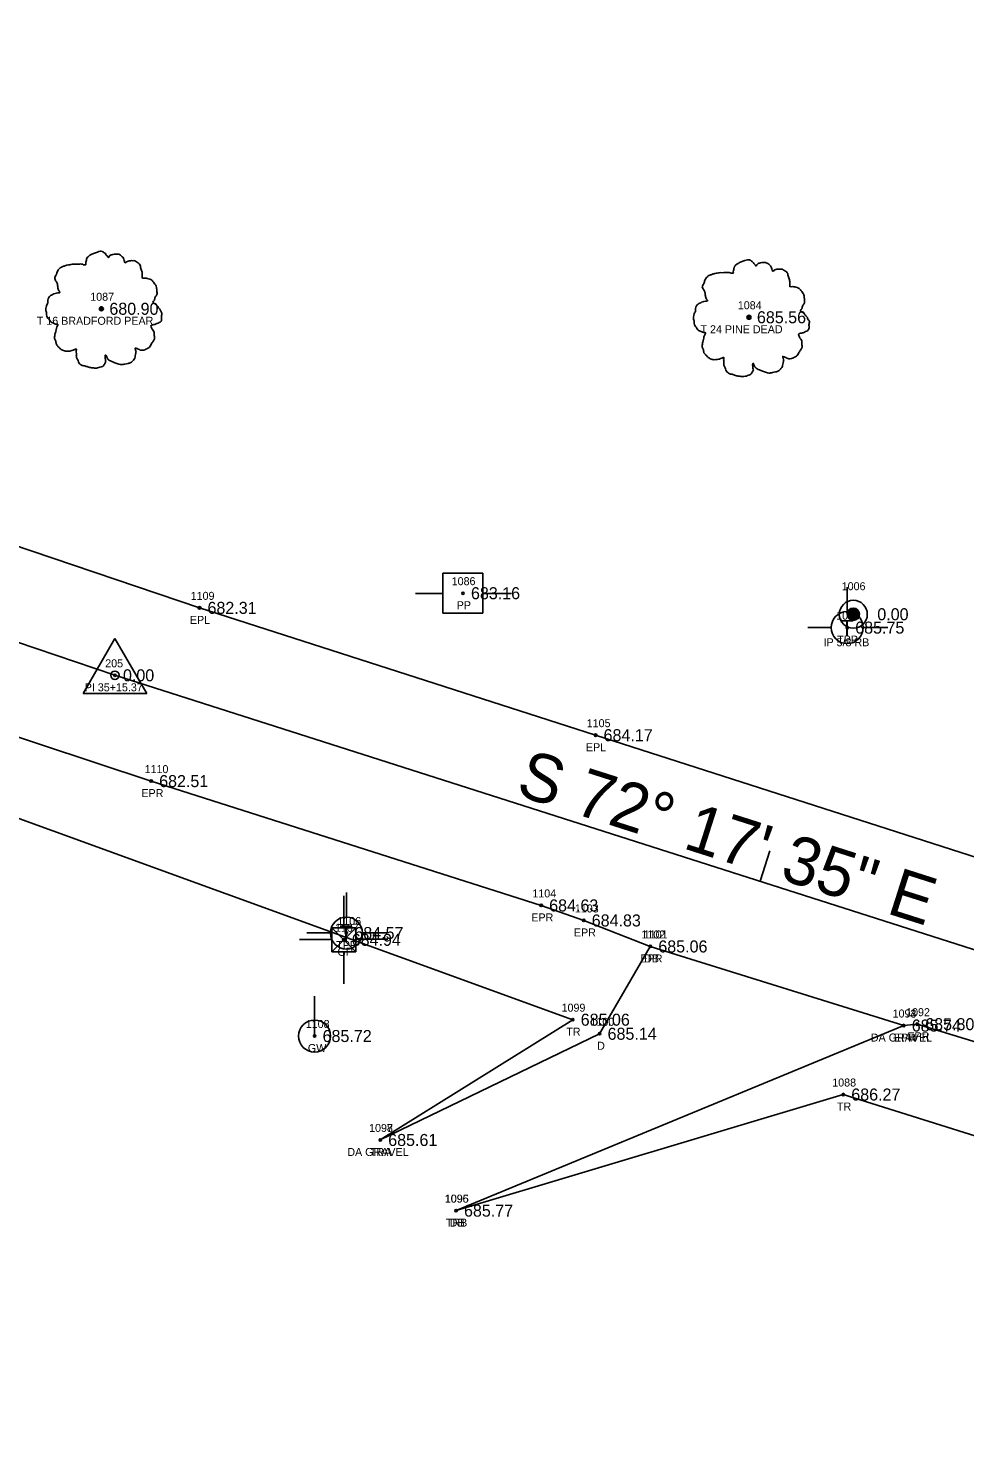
# Model space of a CAD drawing. Extents: x 1655137 to 1657928, y 1003994 to 1005407.
# Drawn here: x 1656847.1 to 1656964.1, y 1004369.3 to 1004544.3 of the extents above; entities that cross this region are included whole.
import ezdxf

# ---------------------------------------------------------------- set-up
doc = ezdxf.new("R2010")
doc.units = 0
for name, color, linetype in [('RD_EX_Driveway', 7, 'Continuous'), ('RD_EX_Driveway_txCode', 7, 'Continuous'), ('RD_EX_DV_Prop_txCode', 7, 'Continuous'), ('RD_EX_DV_PropPin', 7, 'Continuous'), ('RD_EX_Road', 7, 'Continuous'), ('RD_EX_Road_txCode', 7, 'Continuous'), ('RD_EX_TX_Driveway_ELEV', 7, 'Continuous'), ('RD_EX_TX_DV_Prop_ELEV', 7, 'Continuous'), ('RD_EX_TX_Road_ELEV', 7, 'Continuous'), ('RD_EX_TX_UT_ELEV', 7, 'Continuous'), ('RD_EX_TX_VEG_ELEV', 7, 'Continuous'), ('RD_EX_UT', 7, 'Continuous'), ('RD_EX_UT_txCode', 7, 'Continuous'), ('RD_EX_VEG', 7, 'Continuous'), ('RD_EX_VEG_txCode', 7, 'Continuous'), ('RD_HC_Cl', 7, 'Continuous'), ('RD_HC_Data', 7, 'Continuous'), ('RD_HC_Data_Tic', 7, 'Continuous'), ('RD_HC_Survey_ELEV', 7, 'Continuous'), ('RD_HC_txCode', 7, 'Continuous'), ('RD_SMD_Locator', 7, 'Continuous')]:
    doc.layers.add(name, color=color, linetype=linetype)

msp = doc.modelspace()

# ---------------------------------------------------------------- linework, layer by layer
at = {"layer": 'RD_EX_Driveway'}
msp.add_line((1656956.49, 1004419.67), (1656900.55, 1004396.54), dxfattribs=at)
msp.add_lwpolyline([(1656891.08, 1004405.37), (1656918.49, 1004418.64), (1656924.83, 1004429.55)], dxfattribs=at)
at = {"layer": 'RD_EX_DV_PropPin'}
for p, q in [((1656949.46, 1004470.87), (1656949.46, 1004471.26)), ((1656949.49, 1004470.76), (1656949.49, 1004471.36)), ((1656949.53, 1004470.69), (1656949.53, 1004471.43)), ((1656949.56, 1004470.64), (1656949.56, 1004471.49)), ((1656949.6, 1004470.59), (1656949.6, 1004471.54)), ((1656949.63, 1004470.55), (1656949.63, 1004471.58)), ((1656949.67, 1004470.51), (1656949.67, 1004471.61)), ((1656949.7, 1004470.48), (1656949.7, 1004471.64)), ((1656949.74, 1004470.45), (1656949.74, 1004471.67)), ((1656949.77, 1004470.43), (1656949.77, 1004471.7)), ((1656949.81, 1004470.41), (1656949.81, 1004471.72)), ((1656949.84, 1004470.39), (1656949.84, 1004471.74)), ((1656949.88, 1004470.37), (1656949.88, 1004471.75)), ((1656949.91, 1004470.35), (1656949.91, 1004471.77)), ((1656949.95, 1004470.34), (1656949.95, 1004471.78)), ((1656949.98, 1004470.33), (1656949.98, 1004471.79)), ((1656950.02, 1004470.32), (1656950.02, 1004471.8)), ((1656950.05, 1004470.31), (1656950.05, 1004471.81)), ((1656950.09, 1004470.31), (1656950.09, 1004471.82)), ((1656950.12, 1004470.3), (1656950.12, 1004471.82)), ((1656950.16, 1004470.3), (1656950.16, 1004471.82)), ((1656950.19, 1004470.3), (1656950.19, 1004471.82)), ((1656950.23, 1004470.3), (1656950.23, 1004471.82)), ((1656950.26, 1004470.3), (1656950.26, 1004471.82)), ((1656950.3, 1004470.31), (1656950.3, 1004471.82)), ((1656950.33, 1004470.31), (1656950.33, 1004471.81)), ((1656950.37, 1004470.32), (1656950.37, 1004471.8)), ((1656950.4, 1004470.33), (1656950.4, 1004471.79)), ((1656950.44, 1004470.34), (1656950.44, 1004471.78)), ((1656950.47, 1004470.35), (1656950.47, 1004471.77)), ((1656950.51, 1004470.37), (1656950.51, 1004471.75)), ((1656950.54, 1004470.39), (1656950.54, 1004471.74)), ((1656950.58, 1004470.41), (1656950.58, 1004471.72)), ((1656950.61, 1004470.43), (1656950.61, 1004471.7)), ((1656950.65, 1004470.45), (1656950.65, 1004471.67)), ((1656950.68, 1004470.48), (1656950.68, 1004471.64)), ((1656950.72, 1004470.51), (1656950.72, 1004471.61)), ((1656950.75, 1004470.55), (1656950.75, 1004471.58)), ((1656950.79, 1004470.59), (1656950.79, 1004471.54)), ((1656950.82, 1004470.64), (1656950.82, 1004471.49)), ((1656950.86, 1004470.69), (1656950.86, 1004471.43)), ((1656950.89, 1004470.76), (1656950.89, 1004471.36)), ((1656950.93, 1004470.87), (1656950.93, 1004471.26))]:
    msp.add_line(p, q, dxfattribs=at)
for radius in [1.75, 0.761]:
    msp.add_circle((1656950.19, 1004471.06), radius, dxfattribs=at)
at = {"layer": 'RD_EX_Road'}
for points in [[(1657064.39, 1004409.09), (1657015.67, 1004424.64), (1656965.82, 1004440.6), (1656917.99, 1004455.95), (1656868.5, 1004471.86), (1656826.53, 1004486.06), (1656801.74, 1004494.51), (1656772.14, 1004504.27), (1656723.45, 1004520.92), (1656674.94, 1004537.34), (1656626.5, 1004553.88), (1656578.27, 1004569.52), (1656529.18, 1004584.75), (1656481.5, 1004600.51), (1656432.67, 1004617.14), (1656404.34, 1004625.82)], [(1657057.77, 1004388.92), (1657009.7, 1004404.08), (1656958.18, 1004419.84), (1656956.49, 1004419.67), (1656924.83, 1004429.55), (1656916.51, 1004432.8), (1656911.19, 1004434.68), (1656862.46, 1004450.21), (1656813.53, 1004466.42), (1656765.51, 1004482.33), (1656716.81, 1004499.14), (1656668.6, 1004515.93), (1656620.24, 1004532.54), (1656571.72, 1004548.37), (1656523.3, 1004563.77), (1656474.37, 1004580.29), (1656426.43, 1004596.82), (1656398.22, 1004606.78)]]:
    msp.add_lwpolyline(points, dxfattribs=at)
at = {"layer": 'RD_EX_UT'}
for p, q in [((1656903.91, 1004476.2), (1656898.91, 1004476.2)), ((1656898.91, 1004476.2), (1656898.91, 1004471.2)), ((1656903.91, 1004471.2), (1656903.91, 1004476.2)), ((1656949.43, 1004474.46), (1656949.43, 1004471.39)), ((1656895.48, 1004473.64), (1656898.95, 1004473.64)), ((1656903.84, 1004473.64), (1656907.48, 1004473.64)), ((1656898.91, 1004471.2), (1656903.91, 1004471.2)), ((1656944.5, 1004469.41), (1656947.43, 1004469.41)), ((1656951.43, 1004469.41), (1656954.5, 1004469.41)), ((1656886.52, 1004431.88), (1656886.52, 1004435.88)), ((1656886.85, 1004436.3), (1656886.85, 1004433.23)), ((1656885, 1004430.43), (1656881, 1004430.43)), ((1656881.92, 1004431.25), (1656884.85, 1004431.25)), ((1656888.02, 1004431.88), (1656885.02, 1004428.88)), ((1656885.02, 1004431.88), (1656888.02, 1004428.88)), ((1656888.02, 1004431.88), (1656885.02, 1004431.88)), ((1656885.02, 1004431.88), (1656885.02, 1004428.88)), ((1656888.02, 1004428.88), (1656888.02, 1004431.88)), ((1656888.04, 1004430.45), (1656892.05, 1004430.45)), ((1656888.85, 1004431.25), (1656891.92, 1004431.25)), ((1656885.02, 1004428.88), (1656888.02, 1004428.88)), ((1656886.52, 1004428.88), (1656886.52, 1004424.88)), ((1656882.88, 1004418.36), (1656882.88, 1004423.36))]:
    msp.add_line(p, q, dxfattribs=at)
for centre in [(1656949.43, 1004469.39), (1656886.85, 1004431.23), (1656882.88, 1004418.36)]:
    msp.add_circle(centre, 2, dxfattribs=at)
at = {"layer": 'RD_EX_VEG'}
for points in [[(1656891.08, 1004405.37), (1656915.13, 1004420.4), (1656763.49, 1004475.48), (1656570, 1004542.2), (1656467.82, 1004565.09), (1656367.55, 1004594.62), (1656280.9, 1004634.63), (1656273.57, 1004608.65)], [(1657052.06, 1004369.26), (1656992.01, 1004397.53), (1656948.94, 1004411.05), (1656900.55, 1004396.54)]]:
    msp.add_lwpolyline(points, dxfattribs=at)
for centre, radius in [((1656856.24, 1004509.23), 0.25), ((1656856.22, 1004509.21), 0.0001), ((1656937.15, 1004508.17), 0.25), ((1656937.13, 1004508.15), 0.0001)]:
    msp.add_circle(centre, radius, dxfattribs=at)
for points in [[(1656856.37, 1004516.39), (1656856.07, 1004516.42), (1656855.74, 1004516.32), (1656855.49, 1004516.22), (1656855.27, 1004516.14), (1656855.04, 1004516.04), (1656854.74, 1004515.87), (1656854.52, 1004515.67), (1656854.39, 1004515.42), (1656854.34, 1004515.19), (1656854.29, 1004514.92), (1656854.29, 1004514.74), (1656854.17, 1004514.72), (1656854.02, 1004514.74), (1656853.77, 1004514.82), (1656853.52, 1004514.82), (1656853.27, 1004514.82), (1656852.92, 1004514.79), (1656852.57, 1004514.79), (1656852.29, 1004514.74), (1656851.97, 1004514.69), (1656851.59, 1004514.57), (1656851.24, 1004514.44), (1656850.94, 1004514.19), (1656850.69, 1004513.72), (1656850.57, 1004513.37), (1656850.42, 1004513.12), (1656850.57, 1004512.67), (1656850.74, 1004512.32), (1656850.77, 1004512.12), (1656850.84, 1004511.69), (1656850.94, 1004511.47), (1656851.07, 1004511.27), (1656850.99, 1004511.24), (1656850.62, 1004511.19), (1656850.32, 1004511.09), (1656849.9, 1004510.87), (1656849.67, 1004510.64), (1656849.57, 1004510.32), (1656849.55, 1004509.97), (1656849.45, 1004509.77), (1656849.37, 1004509.5), (1656849.35, 1004509.42), (1656849.3, 1004509.1), (1656849.4, 1004508.65), (1656849.42, 1004508.3), (1656849.55, 1004508.07), (1656849.7, 1004507.9), (1656849.87, 1004507.65), (1656850.27, 1004507.42), (1656850.59, 1004507.32), (1656850.79, 1004507.3), (1656850.62, 1004506.8), (1656850.57, 1004506.45), (1656850.44, 1004506.05), (1656850.44, 1004505.97), (1656850.39, 1004505.5), (1656850.54, 1004505.17), (1656850.62, 1004504.8), (1656850.79, 1004504.57), (1656851.07, 1004504.27), (1656851.39, 1004504.05), (1656851.89, 1004503.92), (1656852.29, 1004503.95), (1656852.87, 1004504.12), (1656853.12, 1004504.2), (1656853.09, 1004504.02), (1656853.12, 1004503.65), (1656853.12, 1004503.22), (1656853.27, 1004502.9), (1656853.37, 1004502.62), (1656853.52, 1004502.37), (1656853.84, 1004502.15), (1656854.24, 1004502.07), (1656854.67, 1004501.92), (1656855.12, 1004501.85), (1656855.62, 1004501.82), (1656856.22, 1004501.97), (1656856.49, 1004502.1), (1656856.59, 1004502.27), (1656856.79, 1004502.65), (1656856.74, 1004502.87), (1656856.77, 1004503.47), (1656856.87, 1004503.3), (1656857.04, 1004502.95), (1656857.54, 1004502.65), (1656857.94, 1004502.47), (1656858.42, 1004502.32), (1656858.72, 1004502.25), (1656859.19, 1004502.32), (1656859.57, 1004502.4), (1656859.94, 1004502.52), (1656860.24, 1004502.8), (1656860.42, 1004503.07), (1656860.47, 1004503.35), (1656860.54, 1004503.72), (1656860.59, 1004503.9)], [(1656860.59, 1004503.9), (1656860.52, 1004504.07), (1656860.47, 1004504.32), (1656860.54, 1004504.3), (1656860.72, 1004504.25), (1656860.99, 1004504.12), (1656861.22, 1004504.05), (1656861.54, 1004504.07), (1656861.81, 1004504.17), (1656862.26, 1004504.45), (1656862.54, 1004504.92), (1656862.81, 1004505.32), (1656862.89, 1004505.65), (1656862.84, 1004505.87), (1656862.81, 1004506.37), (1656862.61, 1004506.62), (1656862.56, 1004506.75), (1656862.46, 1004507.15), (1656862.54, 1004507.2), (1656862.81, 1004507.25), (1656863.19, 1004507.37), (1656863.46, 1004507.5), (1656863.69, 1004507.67), (1656863.76, 1004507.9), (1656863.74, 1004508.3), (1656863.79, 1004508.7), (1656863.71, 1004508.85), (1656863.61, 1004509), (1656863.54, 1004509.2), (1656863.39, 1004509.35), (1656863.29, 1004509.5), (1656863.19, 1004509.6), (1656863.06, 1004509.75), (1656862.89, 1004509.87), (1656862.74, 1004509.92), (1656862.69, 1004510.07), (1656862.84, 1004510.27), (1656862.89, 1004510.37), (1656862.91, 1004510.59), (1656863.14, 1004510.94), (1656863.19, 1004511.34), (1656863.14, 1004511.77), (1656863.09, 1004512.04), (1656862.94, 1004512.32), (1656862.74, 1004512.57), (1656862.61, 1004512.74), (1656862.44, 1004512.87), (1656862.11, 1004512.99), (1656861.86, 1004513.04), (1656861.52, 1004513.04), (1656861.32, 1004513.09), (1656861.34, 1004513.14), (1656861.34, 1004513.29), (1656861.34, 1004513.57), (1656861.27, 1004514.02), (1656861.12, 1004514.52), (1656861.12, 1004514.54), (1656861.02, 1004514.79), (1656860.79, 1004514.99), (1656860.62, 1004515.09), (1656860.42, 1004515.22), (1656860.17, 1004515.24), (1656859.87, 1004515.24), (1656859.59, 1004515.19), (1656859.39, 1004515.09), (1656859.22, 1004514.97), (1656859.14, 1004515.12), (1656859.04, 1004515.42), (1656858.99, 1004515.57), (1656858.84, 1004515.74), (1656858.62, 1004515.94), (1656858.17, 1004516.07), (1656857.54, 1004515.99), (1656857.24, 1004515.79), (1656857.09, 1004515.62), (1656857.04, 1004515.74), (1656856.84, 1004515.94), (1656856.74, 1004516.12), (1656856.57, 1004516.24), (1656856.42, 1004516.34), (1656856.32, 1004516.39)], [(1656937.28, 1004515.34), (1656936.98, 1004515.36), (1656936.65, 1004515.26), (1656936.4, 1004515.16), (1656936.18, 1004515.09), (1656935.95, 1004514.99), (1656935.65, 1004514.81), (1656935.43, 1004514.61), (1656935.3, 1004514.36), (1656935.25, 1004514.14), (1656935.2, 1004513.86), (1656935.2, 1004513.69), (1656935.08, 1004513.66), (1656934.93, 1004513.69), (1656934.68, 1004513.76), (1656934.43, 1004513.76), (1656934.18, 1004513.76), (1656933.83, 1004513.74), (1656933.48, 1004513.74), (1656933.2, 1004513.69), (1656932.88, 1004513.64), (1656932.51, 1004513.51), (1656932.16, 1004513.39), (1656931.86, 1004513.14), (1656931.61, 1004512.67), (1656931.48, 1004512.32), (1656931.33, 1004512.07), (1656931.48, 1004511.62), (1656931.66, 1004511.27), (1656931.68, 1004511.07), (1656931.76, 1004510.64), (1656931.86, 1004510.42), (1656931.98, 1004510.22), (1656931.91, 1004510.19), (1656931.53, 1004510.14), (1656931.23, 1004510.04), (1656930.81, 1004509.82), (1656930.58, 1004509.59), (1656930.48, 1004509.27), (1656930.46, 1004508.92), (1656930.36, 1004508.72), (1656930.28, 1004508.44), (1656930.26, 1004508.37), (1656930.21, 1004508.04), (1656930.31, 1004507.59), (1656930.33, 1004507.24), (1656930.46, 1004507.02), (1656930.61, 1004506.84), (1656930.78, 1004506.59), (1656931.18, 1004506.37), (1656931.51, 1004506.27), (1656931.71, 1004506.24), (1656931.53, 1004505.74), (1656931.48, 1004505.39), (1656931.36, 1004504.99), (1656931.36, 1004504.92), (1656931.31, 1004504.44), (1656931.46, 1004504.12), (1656931.53, 1004503.74), (1656931.71, 1004503.52), (1656931.98, 1004503.22), (1656932.31, 1004502.99), (1656932.81, 1004502.87), (1656933.2, 1004502.89), (1656933.78, 1004503.07), (1656934.03, 1004503.14), (1656934, 1004502.97), (1656934.03, 1004502.59), (1656934.03, 1004502.17), (1656934.18, 1004501.85), (1656934.28, 1004501.57), (1656934.43, 1004501.32), (1656934.75, 1004501.1), (1656935.15, 1004501.02), (1656935.58, 1004500.87), (1656936.03, 1004500.8), (1656936.53, 1004500.77), (1656937.13, 1004500.92), (1656937.4, 1004501.05), (1656937.5, 1004501.22), (1656937.7, 1004501.6), (1656937.65, 1004501.82), (1656937.68, 1004502.42), (1656937.78, 1004502.24), (1656937.95, 1004501.89), (1656938.45, 1004501.6), (1656938.85, 1004501.42), (1656939.33, 1004501.27), (1656939.63, 1004501.2), (1656940.1, 1004501.27), (1656940.48, 1004501.35), (1656940.85, 1004501.47), (1656941.15, 1004501.75), (1656941.33, 1004502.02), (1656941.38, 1004502.29), (1656941.45, 1004502.67), (1656941.5, 1004502.84)], [(1656941.5, 1004502.84), (1656941.43, 1004503.02), (1656941.38, 1004503.27), (1656941.45, 1004503.24), (1656941.63, 1004503.19), (1656941.9, 1004503.07), (1656942.13, 1004502.99), (1656942.45, 1004503.02), (1656942.73, 1004503.12), (1656943.18, 1004503.39), (1656943.45, 1004503.87), (1656943.73, 1004504.27), (1656943.8, 1004504.59), (1656943.75, 1004504.82), (1656943.73, 1004505.32), (1656943.53, 1004505.57), (1656943.48, 1004505.69), (1656943.38, 1004506.09), (1656943.45, 1004506.14), (1656943.73, 1004506.19), (1656944.1, 1004506.32), (1656944.37, 1004506.44), (1656944.6, 1004506.62), (1656944.67, 1004506.84), (1656944.65, 1004507.24), (1656944.7, 1004507.64), (1656944.62, 1004507.79), (1656944.52, 1004507.94), (1656944.45, 1004508.14), (1656944.3, 1004508.29), (1656944.2, 1004508.44), (1656944.1, 1004508.54), (1656943.98, 1004508.69), (1656943.8, 1004508.82), (1656943.65, 1004508.87), (1656943.6, 1004509.02), (1656943.75, 1004509.22), (1656943.8, 1004509.32), (1656943.83, 1004509.54), (1656944.05, 1004509.89), (1656944.1, 1004510.29), (1656944.05, 1004510.72), (1656944, 1004510.99), (1656943.85, 1004511.27), (1656943.65, 1004511.52), (1656943.53, 1004511.69), (1656943.35, 1004511.82), (1656943.03, 1004511.94), (1656942.78, 1004511.99), (1656942.43, 1004511.99), (1656942.23, 1004512.04), (1656942.25, 1004512.09), (1656942.25, 1004512.24), (1656942.25, 1004512.52), (1656942.18, 1004512.97), (1656942.03, 1004513.46), (1656942.03, 1004513.49), (1656941.93, 1004513.74), (1656941.7, 1004513.94), (1656941.53, 1004514.04), (1656941.33, 1004514.16), (1656941.08, 1004514.19), (1656940.78, 1004514.19), (1656940.5, 1004514.14), (1656940.3, 1004514.04), (1656940.13, 1004513.91), (1656940.05, 1004514.06), (1656939.95, 1004514.36), (1656939.9, 1004514.51), (1656939.75, 1004514.69), (1656939.53, 1004514.89), (1656939.08, 1004515.01), (1656938.45, 1004514.94), (1656938.15, 1004514.74), (1656938, 1004514.56), (1656937.95, 1004514.69), (1656937.75, 1004514.89), (1656937.65, 1004515.06), (1656937.48, 1004515.19), (1656937.33, 1004515.29), (1656937.23, 1004515.34)]]:
    msp.add_spline(points, degree=3, dxfattribs=at)
at = {"layer": 'RD_HC_Cl'}
for p, q in [((1656624.52, 1004542.44), (1656857.94, 1004463.43)), ((1656857.94, 1004463.43), (1657009.06, 1004415.18))]:
    msp.add_line(p, q, dxfattribs=at)
at = {"layer": 'RD_HC_Data'}
for p, q in [((1656853.97, 1004461.14), (1656857.94, 1004468.02)), ((1656857.94, 1004468.02), (1656861.91, 1004461.14)), ((1656853.97, 1004461.14), (1656861.91, 1004461.14))]:
    msp.add_line(p, q, dxfattribs=at)
msp.add_circle((1656857.94, 1004463.43), 0.529, dxfattribs=at)
at = {"layer": 'RD_HC_Data_Tic'}
msp.add_line((1656938.56, 1004437.69), (1656939.78, 1004441.5), dxfattribs=at)
at = {"layer": 'RD_SMD_Locator'}
for centre in [(1656856.24, 1004509.23), (1656937.15, 1004508.17), (1656901.42, 1004473.69), (1656868.5, 1004471.86), (1656950.19, 1004471.06), (1656949.43, 1004469.39), (1656857.94, 1004463.43), (1656917.99, 1004455.95), (1656862.46, 1004450.21), (1656911.19, 1004434.68), (1656916.51, 1004432.8), (1656886.52, 1004430.38), (1656886.85, 1004431.23), (1656924.83, 1004429.55), (1656924.83, 1004429.55), (1656915.13, 1004420.4), (1656956.49, 1004419.67), (1656956.49, 1004419.67), (1656958.18, 1004419.84), (1656882.88, 1004418.36), (1656918.49, 1004418.64), (1656948.94, 1004411.05), (1656891.08, 1004405.37), (1656891.08, 1004405.37), (1656900.55, 1004396.54), (1656900.55, 1004396.54)]:
    msp.add_circle(centre, 0.15, dxfattribs=at)

# ---------------------------------------------------------------- texts
at = {"layer": 'RD_EX_Driveway_txCode'}
for s, p in [('1102', (1656923.72, 1004430.55)), ('DB', (1656924.05, 1004427.55)), ('1093', (1656955.1, 1004420.67)), ('1100', (1656917.35, 1004419.64)), ('DA GRAVEL', (1656952.38, 1004417.67)), ('D', (1656918.18, 1004416.64)), ('1097', (1656889.69, 1004406.37)), ('DA GRAVEL', (1656886.97, 1004403.37)), ('1095', (1656899.17, 1004397.54)), ('DB', (1656899.77, 1004394.54))]:
    msp.add_text(s, height=1, dxfattribs=at).set_placement(p)
at = {"layer": 'RD_EX_DV_Prop_txCode'}
for s, p in [('1006', (1656948.74, 1004474.06)), ('IP 5/8 RB', (1656946.47, 1004467.06))]:
    msp.add_text(s, height=1, dxfattribs=at).set_placement(p)
at = {"layer": 'RD_EX_Road_txCode'}
for s, p in [('1109', (1656867.4, 1004472.86)), ('EPL', (1656867.3, 1004469.86)), ('1105', (1656916.88, 1004456.95)), ('EPL', (1656916.78, 1004453.95)), ('1110', (1656861.64, 1004451.21)), ('EPR', (1656861.24, 1004448.21)), ('1104', (1656910.09, 1004435.68)), ('EPR', (1656909.96, 1004432.68)), ('1103', (1656915.4, 1004433.8)), ('EPR', (1656915.28, 1004430.8)), ('1101', (1656924.01, 1004430.55)), ('EPR', (1656923.6, 1004427.55)), ('1094', (1656955.1, 1004420.67)), ('1092', (1656956.79, 1004420.84)), ('EPR', (1656955.26, 1004417.67)), ('EPR', (1656956.95, 1004417.84))]:
    msp.add_text(s, height=1, dxfattribs=at).set_placement(p)
at = {"layer": 'RD_EX_TX_Driveway_ELEV'}
for s, p in [('685.06', (1656925.83, 1004428.8)), ('685.74', (1656957.49, 1004418.92)), ('685.14', (1656919.49, 1004417.89)), ('685.61', (1656892.08, 1004404.62)), ('685.77', (1656901.55, 1004395.79))]:
    msp.add_text(s, height=1.5, dxfattribs=at).set_placement(p)
at = {"layer": 'RD_EX_TX_DV_Prop_ELEV'}
msp.add_text('0.00', height=1.5, dxfattribs=at).set_placement((1656953.19, 1004470.31))
at = {"layer": 'RD_EX_TX_Road_ELEV'}
for s, p in [('682.31', (1656869.5, 1004471.11)), ('684.17', (1656918.99, 1004455.2)), ('682.51', (1656863.46, 1004449.46)), ('684.63', (1656912.19, 1004433.93)), ('684.83', (1656917.51, 1004432.05)), ('685.06', (1656925.83, 1004428.8)), ('685.74', (1656957.49, 1004418.92)), ('685.80', (1656959.18, 1004419.09))]:
    msp.add_text(s, height=1.5, dxfattribs=at).set_placement(p)
at = {"layer": 'RD_EX_TX_UT_ELEV'}
for s, p in [('685.75', (1656950.43, 1004468.64)), ('684.57', (1656887.85, 1004430.48)), ('684.94', (1656887.52, 1004429.63)), ('685.72', (1656883.88, 1004417.61))]:
    msp.add_text(s, height=1.5, dxfattribs=at).set_placement(p)
at = {"layer": 'RD_EX_TX_VEG_ELEV'}
for s, p in [('680.90', (1656857.24, 1004508.48)), ('685.56', (1656938.15, 1004507.42)), ('685.06', (1656916.13, 1004419.65)), ('686.27', (1656949.94, 1004410.3)), ('685.61', (1656892.08, 1004404.62)), ('685.77', (1656901.55, 1004395.79))]:
    msp.add_text(s, height=1.5, dxfattribs=at).set_placement(p)
at = {"layer": 'RD_EX_UT'}
for p in [(1656948.59, 1004468.35), (1656886, 1004430.19)]:
    msp.add_text('T', height=2, dxfattribs=at).set_placement(p)
at = {"layer": 'RD_EX_UT_txCode'}
for s, p in [('1086', (1656900.01, 1004474.69)), ('PP', (1656900.64, 1004471.69)), ('1085', (1656948.05, 1004470.39)), ('TPP', (1656948.17, 1004467.39)), ('1107', (1656885.42, 1004431.38)), ('1106', (1656885.72, 1004432.23)), ('TPP', (1656885.58, 1004429.23)), ('GP', (1656885.74, 1004428.38)), ('1108', (1656881.78, 1004419.36)), ('GW', (1656882.04, 1004416.36))]:
    msp.add_text(s, height=1, dxfattribs=at).set_placement(p)
at = {"layer": 'RD_EX_VEG_txCode'}
for s, p in [('1087', (1656854.85, 1004510.23)), ('1084', (1656935.76, 1004509.17)), ('T 16 BRADFORD PEAR', (1656848.17, 1004507.23)), ('T 24 PINE DEAD', (1656931.1, 1004506.17)), ('1099', (1656913.74, 1004421.4)), ('TR', (1656914.33, 1004418.4)), ('1088', (1656947.56, 1004412.05)), ('TR', (1656948.15, 1004409.05)), ('1098', (1656889.69, 1004406.37)), ('TRA', (1656889.79, 1004403.37)), ('1096', (1656899.14, 1004397.54)), ('TRB', (1656899.28, 1004394.54))]:
    msp.add_text(s, height=1, dxfattribs=at).set_placement(p)
at = {"layer": 'RD_HC_Data'}
msp.add_text('S 72%%d 17\' 35" E', height=6, rotation=342.2932, dxfattribs=at).set_placement((1656907.85, 1004448.54))
at = {"layer": 'RD_HC_Survey_ELEV'}
for s, p in [('683.16', (1656902.42, 1004472.94)), ('0.00', (1656858.94, 1004462.68))]:
    msp.add_text(s, height=1.5, dxfattribs=at).set_placement(p)
at = {"layer": 'RD_HC_txCode'}
for s, p in [('205', (1656856.72, 1004464.43)), ('PI 35+15.37', (1656854.16, 1004461.43))]:
    msp.add_text(s, height=1, dxfattribs=at).set_placement(p)

doc.saveas('drawing.dxf')
